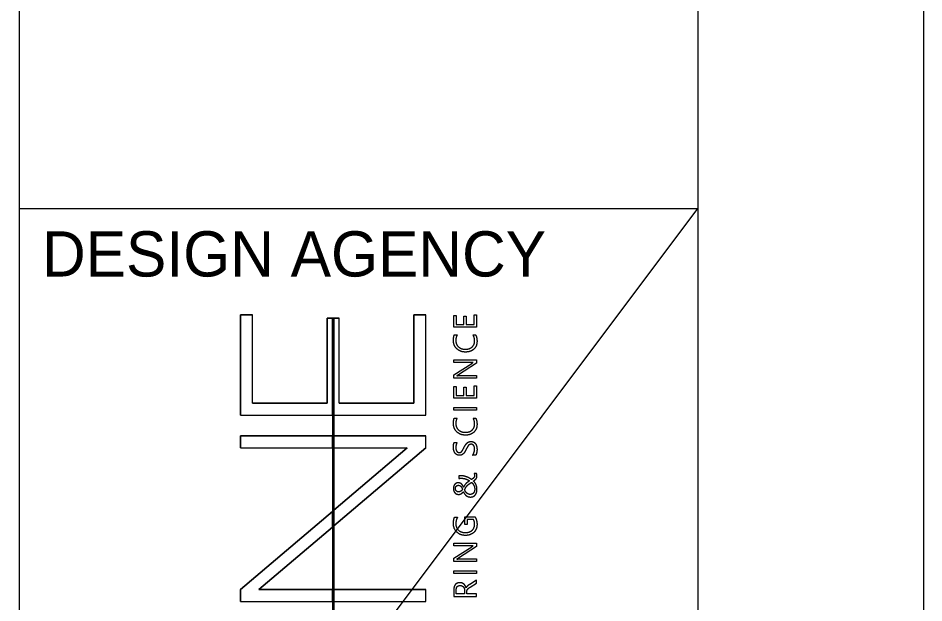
# Model space of a CAD drawing. Extents: x 0 to 104, y 0 to 37.
# Drawn here: x 31.997 to 34, y 4.129 to 5.421 of the extents above; entities that cross this region are included whole.
import ezdxf

# ---------------------------------------------------------------- set-up
doc = ezdxf.new("R2010")
doc.units = 0
for name, color, linetype in [('SC_Scratch3', 7, 'Continuous'), ('SH_Border', 7, 'Continuous'), ('SH_Cut_Line', 7, 'Continuous'), ('SH_Named_Boundary', 7, 'Continuous')]:
    doc.layers.add(name, color=color, linetype=linetype)

msp = doc.modelspace()

# ---------------------------------------------------------------- linework, layer by layer
at = {"layer": 'SC_Scratch3'}
msp.add_lwpolyline([(0, 0), (34, 0), (34, 22), (0, 22)], close=True, dxfattribs=at)
at = {"layer": 'SH_Border'}
msp.add_line((32, 3), (33.5, 5), dxfattribs=at)
at = {"layer": 'SH_Cut_Line'}
for p, q in [((32.489, 4.7652), (32.5153, 4.7652)), ((32.489, 4.5439), (32.489, 4.7652)), ((32.5153, 4.5702), (32.5153, 4.7652)), ((32.6807, 4.5702), (32.6807, 4.7581)), ((32.6807, 4.7581), (32.6923, 4.7581)), ((32.6923, 4.7581), (32.6923, 3.9731)), ((32.6923, 4.7581), (32.6923, 4.5439)), ((32.6923, 4.7581), (32.6954, 4.7581)), ((32.6954, 4.7581), (32.6954, 3.9731)), ((32.6954, 4.7581), (32.6954, 4.5439)), ((32.6954, 4.7581), (32.707, 4.7581)), ((32.707, 4.5702), (32.707, 4.7581)), ((32.8724, 4.7652), (32.8988, 4.7652)), ((32.8724, 4.5702), (32.8724, 4.7652)), ((32.8988, 4.5439), (32.8988, 4.7652)), ((32.9617, 4.7208), (32.968, 4.7208)), ((33.0032, 4.7208), (33.0089, 4.7208)), ((33.0035, 4.6602), (33.0035, 4.6603)), ((32.9676, 4.631), (32.9676, 4.6308)), ((32.5153, 4.5702), (32.6807, 4.5702)), ((32.707, 4.5702), (32.8724, 4.5702)), ((32.489, 4.5439), (32.6923, 4.5439)), ((32.6954, 4.5439), (32.8988, 4.5439)), ((32.9617, 4.5373), (32.968, 4.5373)), ((33.0032, 4.5373), (33.0089, 4.5373)), ((32.489, 4.4717), (32.489, 4.4981)), ((32.489, 4.4981), (32.6923, 4.4981)), ((32.6923, 4.4981), (32.6923, 4.4717)), ((32.6954, 4.4981), (32.6954, 4.4717)), ((32.6954, 4.4981), (32.8988, 4.4981)), ((32.8988, 4.4717), (32.8988, 4.4981)), ((32.489, 4.4717), (32.6923, 4.4717)), ((32.6954, 4.3337), (32.8577, 4.4717)), ((32.8988, 4.4717), (32.6954, 4.2989)), ((32.6954, 4.4717), (32.8577, 4.4717)), ((32.9615, 4.4834), (32.9681, 4.4834)), ((33.009, 4.4549), (33.002, 4.4549)), ((32.9715, 4.4092), (32.9715, 4.4036)), ((33.0109, 4.4148), (33.0055, 4.4148)), ((33.0118, 4.4094), (33.0118, 4.4094)), ((32.9709, 4.3886), (32.9709, 4.3886)), ((33.0068, 4.3798), (33.0068, 4.3798)), ((32.489, 4.158), (32.6923, 4.331)), ((32.6923, 4.331), (32.6923, 4.2962)), ((32.6954, 4.3337), (32.6954, 4.2989)), ((32.9623, 4.318), (32.9689, 4.318)), ((32.6923, 4.2962), (32.5296, 4.158)), ((33.0035, 4.255), (33.0035, 4.2551)), ((32.9676, 4.2258), (32.9676, 4.2256)), ((32.489, 4.1316), (32.489, 4.158)), ((32.5296, 4.158), (32.6923, 4.158)), ((32.6923, 4.158), (32.6923, 4.1316)), ((32.6954, 4.158), (32.6954, 4.1316)), ((32.6954, 4.158), (32.8988, 4.158)), ((32.8988, 4.1316), (32.8988, 4.158)), ((32.9877, 4.1622), (32.9876, 4.1622)), ((32.489, 4.1316), (32.6923, 4.1316)), ((32.6954, 4.1316), (32.8988, 4.1316))]:
    msp.add_line(p, q, dxfattribs=at)
for points in [[(32.489, 4.7652), (32.489, 4.5439), (32.6923, 4.5439), (32.6923, 4.7581), (32.6807, 4.7581), (32.6807, 4.5702), (32.5153, 4.5702), (32.5153, 4.7652)], [(32.707, 4.5702), (32.707, 4.7581), (32.6954, 4.7581), (32.6954, 4.5439), (32.8988, 4.5439), (32.8988, 4.7652), (32.8724, 4.7652), (32.8724, 4.5702)], [(33.011, 4.7652), (33.011, 4.7384), (32.9605, 4.7384), (32.9605, 4.7641), (32.9659, 4.7641), (32.9659, 4.7443), (32.9827, 4.7443), (32.9827, 4.7626), (32.988, 4.7626), (32.988, 4.7443), (33.0057, 4.7443), (33.0057, 4.7652)], [(33.011, 4.6081), (33.011, 4.5813), (32.9605, 4.5813), (32.9605, 4.607), (32.9659, 4.607), (32.9659, 4.5873), (32.9827, 4.5873), (32.9827, 4.6055), (32.988, 4.6055), (32.988, 4.5873), (33.0057, 4.5873), (33.0057, 4.6081)], [(33.011, 4.5607), (33.011, 4.5548), (32.9605, 4.5548), (32.9605, 4.5607)], [(32.489, 4.4981), (32.489, 4.4717), (32.6923, 4.4717), (32.6923, 4.4981)], [(32.6954, 4.4981), (32.6954, 4.4717), (32.8577, 4.4717), (32.6954, 4.3337), (32.6954, 4.2989), (32.8988, 4.4717), (32.8988, 4.4981)], [(32.489, 4.158), (32.489, 4.1316), (32.6923, 4.1316), (32.6923, 4.158), (32.5296, 4.158), (32.6923, 4.2962), (32.6923, 4.331)], [(33.011, 4.1993), (33.011, 4.1934), (32.9605, 4.1934), (32.9605, 4.1993)], [(32.6954, 4.158), (32.6954, 4.1316), (32.8988, 4.1316), (32.8988, 4.158)]]:
    msp.add_lwpolyline(points, close=True, dxfattribs=at)
for points in [[(32.8317, 3.9686), (32.6986, 3.9356), (32.6986, 3.9731), (32.6954, 3.9731), (32.6954, 4.7581), (32.6923, 4.7581), (32.6923, 3.9731), (32.6891, 3.9731), (32.6891, 3.9333), (32.6149, 3.9149)], [(32.9961, 4.66), (32.9605, 4.66), (32.9605, 4.6659), (33.011, 4.6659), (33.011, 4.6586), (32.9708, 4.6326)], [(32.9745, 4.6311), (33.011, 4.6311), (33.011, 4.6252), (32.9605, 4.6252), (32.9605, 4.6328), (33.0001, 4.6581)], [(33.0042, 4.3131), (32.99, 4.3131), (32.99, 4.302), (32.9847, 4.302), (32.9847, 4.319), (33.0076, 4.319)], [(32.9961, 4.2547), (32.9605, 4.2547), (32.9605, 4.2607), (33.011, 4.2607), (33.011, 4.2534), (32.9708, 4.2274)], [(32.9745, 4.2258), (33.011, 4.2258), (33.011, 4.2199), (32.9605, 4.2199), (32.9605, 4.2276), (33.0001, 4.2529)], [(32.9969, 4.1637), (33.011, 4.1721), (33.011, 4.1792), (32.9958, 4.1697)], [(32.9605, 4.158), (32.9605, 4.1429), (33.011, 4.1429), (33.011, 4.1489), (32.9895, 4.1489), (32.9895, 4.1537)], [(32.9842, 4.1569), (32.9842, 4.1489), (32.9659, 4.1489), (32.9659, 4.157)]]:
    msp.add_lwpolyline(points, dxfattribs=at)
for points in [[(32.9597, 4.7089), (32.9597, 4.7161), (32.9617, 4.7208)], [(32.9671, 4.6904), (32.9597, 4.6977), (32.9597, 4.7089)], [(32.968, 4.7208), (32.965, 4.7154), (32.965, 4.7089)], [(32.965, 4.7089), (32.965, 4.7002), (32.9708, 4.6947)], [(33.0011, 4.6944), (33.0066, 4.6994), (33.0066, 4.7077)], [(33.0066, 4.7077), (33.0066, 4.7153), (33.0032, 4.7208)], [(33.0119, 4.7069), (33.0119, 4.6961), (33.0049, 4.6896)], [(33.0089, 4.7208), (33.0119, 4.7152), (33.0119, 4.7069)], [(32.9867, 4.6831), (32.9746, 4.6831), (32.9671, 4.6904)], [(32.9708, 4.6947), (32.9766, 4.6893), (32.9864, 4.6893)], [(32.9864, 4.6893), (32.9956, 4.6893), (33.0011, 4.6944)], [(33.0049, 4.6896), (32.998, 4.6831), (32.9867, 4.6831)], [(33.0035, 4.6603), (33.0013, 4.66), (32.9961, 4.66)], [(33.0001, 4.6581), (33.0026, 4.6597), (33.0035, 4.6602)], [(32.9708, 4.6326), (32.9692, 4.6316), (32.9676, 4.631)], [(32.9676, 4.6308), (32.9692, 4.6311), (32.9745, 4.6311)], [(32.9597, 4.5253), (32.9597, 4.5325), (32.9617, 4.5373)], [(32.968, 4.5373), (32.965, 4.5318), (32.965, 4.5253)], [(33.0066, 4.5241), (33.0066, 4.5317), (33.0032, 4.5373)], [(33.0089, 4.5373), (33.0119, 4.5316), (33.0119, 4.5233)], [(32.9671, 4.5068), (32.9597, 4.5141), (32.9597, 4.5253)], [(32.965, 4.5253), (32.965, 4.5166), (32.9708, 4.5112)], [(32.9867, 4.4995), (32.9746, 4.4995), (32.9671, 4.5068)], [(32.9708, 4.5112), (32.9766, 4.5057), (32.9864, 4.5057)], [(32.9864, 4.5057), (32.9956, 4.5057), (33.0011, 4.5108)], [(33.0011, 4.5108), (33.0066, 4.5159), (33.0066, 4.5241)], [(33.0119, 4.5233), (33.0119, 4.5125), (33.0049, 4.506)], [(33.0049, 4.506), (32.998, 4.4995), (32.9867, 4.4995)], [(32.9597, 4.4725), (32.9597, 4.4799), (32.9615, 4.4834)], [(32.9605, 4.466), (32.9597, 4.4692), (32.9597, 4.4725)], [(32.9681, 4.4834), (32.965, 4.4789), (32.965, 4.4719)], [(32.965, 4.4719), (32.965, 4.4699), (32.9654, 4.468)], [(32.9654, 4.468), (32.9658, 4.4661), (32.9667, 4.4645)], [(32.9785, 4.464), (32.9797, 4.4654), (32.9808, 4.4674)], [(32.9808, 4.4674), (32.9819, 4.4694), (32.9832, 4.4721)], [(32.9832, 4.4721), (32.9845, 4.4748), (32.986, 4.4772)], [(32.9876, 4.4675), (32.9862, 4.4648), (32.9849, 4.4625)], [(32.986, 4.4772), (32.9875, 4.4797), (32.9893, 4.4815)], [(32.99, 4.4721), (32.9888, 4.47), (32.9876, 4.4675)], [(32.9893, 4.4815), (32.9911, 4.4833), (32.9933, 4.4844)], [(32.9924, 4.4759), (32.9911, 4.4743), (32.99, 4.4721)], [(32.9951, 4.4784), (32.9936, 4.4775), (32.9924, 4.4759)], [(32.9933, 4.4844), (32.9955, 4.4855), (32.9983, 4.4855)], [(32.9987, 4.4793), (32.9967, 4.4793), (32.9951, 4.4784)], [(32.9983, 4.4855), (33.002, 4.4855), (33.0046, 4.484)], [(33.0045, 4.4766), (33.0025, 4.4793), (32.9987, 4.4793)], [(33.0066, 4.4684), (33.0066, 4.4739), (33.0045, 4.4766)], [(33.0046, 4.484), (33.0072, 4.4826), (33.0088, 4.4801)], [(33.0062, 4.465), (33.0066, 4.4668), (33.0066, 4.4684)], [(33.0088, 4.4801), (33.0104, 4.4776), (33.0112, 4.4743)], [(33.0112, 4.4743), (33.0119, 4.4711), (33.0119, 4.4675)], [(33.0119, 4.4675), (33.0119, 4.4663), (33.0117, 4.4645)], [(32.9629, 4.4604), (32.9613, 4.4629), (32.9605, 4.466)], [(32.9671, 4.4564), (32.9646, 4.458), (32.9629, 4.4604)], [(32.9667, 4.4645), (32.9677, 4.463), (32.9691, 4.4621)], [(32.9732, 4.4549), (32.9697, 4.4549), (32.9671, 4.4564)], [(32.9691, 4.4621), (32.9705, 4.4611), (32.9726, 4.4611)], [(32.9726, 4.4611), (32.9746, 4.4611), (32.976, 4.4618)], [(32.9781, 4.4559), (32.976, 4.4549), (32.9732, 4.4549)], [(32.976, 4.4618), (32.9774, 4.4626), (32.9785, 4.464)], [(32.9818, 4.4586), (32.9802, 4.4569), (32.9781, 4.4559)], [(32.9849, 4.4625), (32.9835, 4.4602), (32.9818, 4.4586)], [(33.002, 4.4549), (33.0031, 4.4561), (33.0039, 4.4577)], [(33.0039, 4.4577), (33.0048, 4.4594), (33.0053, 4.4612)], [(33.0053, 4.4612), (33.0059, 4.4631), (33.0062, 4.465)], [(33.0102, 4.4575), (33.0097, 4.4558), (33.009, 4.4549)], [(33.0111, 4.461), (33.0108, 4.4591), (33.0102, 4.4575)], [(33.0117, 4.4645), (33.0115, 4.4628), (33.0111, 4.461)], [(32.9737, 4.4095), (32.9727, 4.4095), (32.9715, 4.4092)], [(32.9762, 4.4096), (32.9748, 4.4096), (32.9737, 4.4095)], [(32.9827, 4.409), (32.9794, 4.4096), (32.9762, 4.4096)], [(32.989, 4.4072), (32.9859, 4.4083), (32.9827, 4.409)], [(32.9948, 4.4045), (32.992, 4.406), (32.989, 4.4072)], [(33.0061, 4.4079), (33.0057, 4.4067), (33.0048, 4.4057)], [(33.0055, 4.4148), (33.0059, 4.4136), (33.0062, 4.4125)], [(33.0065, 4.4104), (33.0065, 4.409), (33.0061, 4.4079)], [(33.0062, 4.4125), (33.0065, 4.4114), (33.0065, 4.4104)], [(33.0116, 4.4121), (33.0114, 4.4135), (33.0109, 4.4148)], [(33.0113, 4.4059), (33.0118, 4.4074), (33.0118, 4.4094)], [(33.0118, 4.4094), (33.0118, 4.4107), (33.0116, 4.4121)], [(32.9604, 4.3867), (32.9597, 4.3844), (32.9597, 4.3817)], [(32.9626, 4.3906), (32.9612, 4.389), (32.9604, 4.3867)], [(32.966, 4.3931), (32.964, 4.3922), (32.9626, 4.3906)], [(32.9646, 4.3841), (32.965, 4.3853), (32.9658, 4.3863)], [(32.9658, 4.3863), (32.9666, 4.3873), (32.9679, 4.388)], [(32.9704, 4.3941), (32.9679, 4.3941), (32.966, 4.3931)], [(32.9679, 4.388), (32.9691, 4.3886), (32.9709, 4.3886)], [(32.9774, 4.3916), (32.9746, 4.3941), (32.9704, 4.3941)], [(32.9709, 4.3886), (32.974, 4.3886), (32.9761, 4.3864)], [(32.9715, 4.4036), (32.9727, 4.4039), (32.9739, 4.404)], [(32.9739, 4.404), (32.9751, 4.4042), (32.9764, 4.4042)], [(32.9761, 4.3864), (32.9781, 4.3843), (32.9797, 4.3798)], [(32.9764, 4.4042), (32.9816, 4.4042), (32.9864, 4.4027)], [(32.9822, 4.3844), (32.9802, 4.3892), (32.9774, 4.3916)], [(32.9845, 4.3888), (32.9831, 4.3868), (32.9822, 4.3844)], [(32.9876, 4.3925), (32.9859, 4.3908), (32.9845, 4.3888)], [(32.9864, 4.4027), (32.9912, 4.4013), (32.9952, 4.3984)], [(32.987, 4.3836), (32.9882, 4.3857), (32.9899, 4.3876)], [(32.9912, 4.3956), (32.9893, 4.3941), (32.9876, 4.3925)], [(32.9899, 4.3876), (32.9917, 4.3894), (32.994, 4.3912)], [(32.9952, 4.3984), (32.9931, 4.397), (32.9912, 4.3956)], [(32.994, 4.3912), (32.9964, 4.393), (32.9998, 4.3952)], [(32.9998, 4.4014), (32.9975, 4.403), (32.9948, 4.4045)], [(33.0027, 4.4036), (33.0015, 4.4026), (32.9998, 4.4014)], [(32.9998, 4.3952), (33.0012, 4.3939), (33.0025, 4.3924)], [(33.0025, 4.3924), (33.0037, 4.3908), (33.0047, 4.3889)], [(33.0048, 4.4057), (33.004, 4.4047), (33.0027, 4.4036)], [(33.004, 4.3979), (33.0059, 4.3993), (33.0073, 4.4005)], [(33.007, 4.3947), (33.0055, 4.3965), (33.004, 4.3979)], [(33.0047, 4.3889), (33.0057, 4.387), (33.0063, 4.3848)], [(33.0095, 4.3906), (33.0084, 4.3928), (33.007, 4.3947)], [(33.0073, 4.4005), (33.0087, 4.4017), (33.0098, 4.403)], [(33.0112, 4.3856), (33.0105, 4.3883), (33.0095, 4.3906)], [(33.0098, 4.403), (33.0108, 4.4043), (33.0113, 4.4059)], [(32.9597, 4.3817), (32.9597, 4.3789), (32.9604, 4.3765)], [(32.9604, 4.3765), (32.9612, 4.3741), (32.9627, 4.3723)], [(32.9627, 4.3723), (32.9641, 4.3706), (32.9663, 4.3696)], [(32.9643, 4.3817), (32.9643, 4.3829), (32.9646, 4.3841)], [(32.9661, 4.3761), (32.9643, 4.3782), (32.9643, 4.3817)], [(32.9712, 4.374), (32.968, 4.3741), (32.9661, 4.3761)], [(32.9663, 4.3696), (32.9684, 4.3685), (32.9712, 4.3685)], [(32.9739, 4.3745), (32.9727, 4.374), (32.9712, 4.374)], [(32.9712, 4.3685), (32.9731, 4.3685), (32.9747, 4.3691)], [(32.9763, 4.3757), (32.9752, 4.3749), (32.9739, 4.3745)], [(32.9747, 4.3691), (32.9763, 4.3696), (32.9776, 4.3704)], [(32.9782, 4.3776), (32.9774, 4.3765), (32.9763, 4.3757)], [(32.9776, 4.3704), (32.979, 4.3712), (32.98, 4.3723)], [(32.9797, 4.3798), (32.9791, 4.3786), (32.9782, 4.3776)], [(32.98, 4.3723), (32.981, 4.3733), (32.9818, 4.3744)], [(32.9818, 4.3744), (32.9843, 4.3688), (32.9881, 4.3657)], [(32.9847, 4.3788), (32.9857, 4.3815), (32.987, 4.3836)], [(32.9866, 4.3747), (32.9856, 4.3765), (32.9847, 4.3788)], [(32.9892, 4.3715), (32.9877, 4.3728), (32.9866, 4.3747)], [(32.9926, 4.3693), (32.9906, 4.3701), (32.9892, 4.3715)], [(32.9971, 4.3685), (32.9945, 4.3685), (32.9926, 4.3693)], [(33.0013, 4.3694), (32.9995, 4.3685), (32.9971, 4.3685)], [(33.0044, 4.3718), (33.0032, 4.3703), (33.0013, 4.3694)], [(33.0035, 4.3639), (33.0062, 4.3652), (33.0081, 4.3674)], [(33.0062, 4.3754), (33.0056, 4.3734), (33.0044, 4.3718)], [(33.0068, 4.3798), (33.0068, 4.3775), (33.0062, 4.3754)], [(33.0063, 4.3848), (33.0068, 4.3825), (33.0068, 4.3798)], [(33.0081, 4.3674), (33.0099, 4.3697), (33.0109, 4.3728)], [(33.0109, 4.3728), (33.0118, 4.376), (33.0118, 4.3798)], [(33.0118, 4.3798), (33.0118, 4.383), (33.0112, 4.3856)], [(32.9881, 4.3657), (32.9919, 4.3627), (32.9973, 4.3627)], [(32.9973, 4.3627), (33.0008, 4.3627), (33.0035, 4.3639)], [(32.9597, 4.3041), (32.9597, 4.3124), (32.9623, 4.318)], [(32.9689, 4.318), (32.965, 4.3118), (32.965, 4.3035)], [(33.0066, 4.3028), (33.0066, 4.3087), (33.0042, 4.3131)], [(33.0076, 4.319), (33.0119, 4.3114), (33.0119, 4.3021)], [(32.9672, 4.2853), (32.9597, 4.2927), (32.9597, 4.3041)], [(32.965, 4.3035), (32.965, 4.295), (32.9709, 4.2895)], [(32.9709, 4.2895), (32.9767, 4.2841), (32.986, 4.2841)], [(32.986, 4.2841), (32.9956, 4.2841), (33.0011, 4.2891)], [(33.0011, 4.2891), (33.0066, 4.2942), (33.0066, 4.3028)], [(33.0119, 4.3021), (33.0119, 4.2913), (33.0049, 4.2846)], [(32.9864, 4.2779), (32.9747, 4.2779), (32.9672, 4.2853)], [(33.0049, 4.2846), (32.9979, 4.2779), (32.9864, 4.2779)], [(33.0035, 4.2551), (33.0013, 4.2547), (32.9961, 4.2547)], [(33.0001, 4.2529), (33.0026, 4.2545), (33.0035, 4.255)], [(32.9708, 4.2274), (32.9692, 4.2264), (32.9676, 4.2258)], [(32.9676, 4.2256), (32.9692, 4.2258), (32.9745, 4.2258)], [(32.9638, 4.169), (32.9622, 4.1669), (32.9613, 4.1641)], [(32.9681, 4.1722), (32.9655, 4.1711), (32.9638, 4.169)], [(32.974, 4.1734), (32.9706, 4.1734), (32.9681, 4.1722)], [(32.9681, 4.1646), (32.9704, 4.1672), (32.9745, 4.1672)], [(32.9788, 4.1726), (32.9766, 4.1734), (32.974, 4.1734)], [(32.9745, 4.1672), (32.9767, 4.1672), (32.9785, 4.1664)], [(32.9785, 4.1664), (32.9803, 4.1656), (32.9816, 4.1643)], [(32.9827, 4.1703), (32.981, 4.1718), (32.9788, 4.1726)], [(32.9857, 4.1668), (32.9845, 4.1689), (32.9827, 4.1703)], [(32.9876, 4.1622), (32.9869, 4.1648), (32.9857, 4.1668)], [(32.9907, 4.1662), (32.9897, 4.1653), (32.989, 4.1644)], [(32.9929, 4.1678), (32.9917, 4.167), (32.9907, 4.1662)], [(32.9958, 4.1697), (32.9942, 4.1687), (32.9929, 4.1678)], [(32.9613, 4.1641), (32.9605, 4.1613), (32.9605, 4.158)], [(32.9659, 4.157), (32.9659, 4.1619), (32.9681, 4.1646)], [(32.9816, 4.1643), (32.9828, 4.1629), (32.9835, 4.161)], [(32.9835, 4.161), (32.9842, 4.1591), (32.9842, 4.1569)], [(32.989, 4.1644), (32.9883, 4.1635), (32.9877, 4.1622)], [(32.9895, 4.1537), (32.9895, 4.1554), (32.9899, 4.1567)], [(32.9899, 4.1567), (32.9904, 4.158), (32.9912, 4.1592)], [(32.9912, 4.1592), (32.9921, 4.1603), (32.9935, 4.1614)], [(32.9935, 4.1614), (32.9949, 4.1625), (32.9969, 4.1637)]]:
    msp.add_open_spline(points, degree=2, dxfattribs=at)
at = {"layer": 'SH_Named_Boundary'}
for p, q in [((32, 0.5), (32, 21.5)), ((32, 5), (33.5, 5))]:
    msp.add_line(p, q, dxfattribs=at)
msp.add_lwpolyline([(1.5, 21.5), (33.5, 21.5), (33.5, 0.5), (1.5, 0.5)], close=True, dxfattribs=at)

# ---------------------------------------------------------------- texts
at = {"layer": 'SH_Cut_Line'}
msp.add_text('DESIGN AGENCY', height=0.1, dxfattribs=at).set_placement((32.05, 4.85))

doc.saveas('drawing.dxf')
